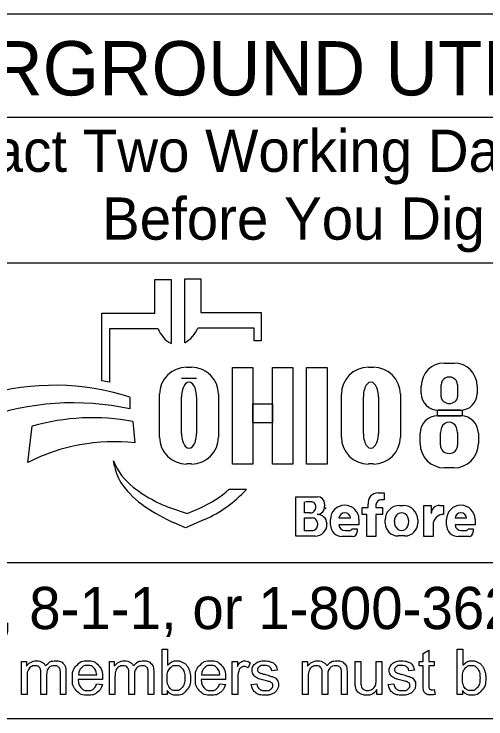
# Model space of a CAD drawing. Extents: x 0 to 34, y 0 to 22.
# Drawn here: x 3.216 to 4.78, y 2.954 to 5.292 of the extents above; entities that cross this region are included whole.
import ezdxf

# ---------------------------------------------------------------- set-up
doc = ezdxf.new("R2010")
doc.units = 0
doc.layers.add('SH_Data', color=7, linetype='Continuous')
doc.layers.add('SH_Text', color=7, linetype='Continuous')

msp = doc.modelspace()

# ---------------------------------------------------------------- linework, layer by layer
at = {"layer": 'SH_Data'}
for p, q in [((6.5766, 5.2918), (2.3266, 5.2918)), ((2.3266, 4.9502), (6.5766, 4.9502)), ((2.3266, 4.4668), (6.5766, 4.4668)), ((6.5766, 3.4722), (2.3266, 3.4722)), ((6.5766, 2.9543), (2.3266, 2.9543))]:
    msp.add_line(p, q, dxfattribs=at)
at = {"layer": 'SH_Text'}
for p, q in [((3.6827, 4.2998), (3.6827, 4.4113)), ((3.6827, 4.4113), (3.7363, 4.4113)), ((3.7363, 4.4113), (3.7363, 4.1992)), ((3.782, 4.2015), (3.782, 4.4136)), ((3.782, 4.4136), (3.8356, 4.4136)), ((3.8356, 4.4136), (3.8356, 4.3021)), ((3.8356, 4.3021), (4.0349, 4.3021)), ((4.0349, 4.3021), (4.0349, 4.2083)), ((3.5067, 4.0759), (3.5067, 4.2998)), ((3.5067, 4.2998), (3.6827, 4.2998)), ((3.5319, 4.2484), (3.5319, 4.0715)), ((3.6931, 4.2484), (3.5319, 4.2484)), ((4.0116, 4.2507), (3.8252, 4.2507)), ((4.0116, 4.2083), (4.0116, 4.2507)), ((4.0349, 4.2083), (4.0116, 4.2083)), ((3.7876, 4.1206), (3.8042, 4.1206)), ((4.3907, 4.1206), (4.4072, 4.1206)), ((4.6422, 4.1346), (4.675, 4.1346)), ((3.8209, 4.0836), (3.7711, 4.0836)), ((4.5659, 4.034), (4.5659, 4.0583)), ((4.6321, 4.0226), (4.6321, 4.0619)), ((4.6862, 4.0619), (4.6862, 4.0226)), ((4.7513, 4.0583), (4.7513, 4.034)), ((3.6, 4.0212), (3.6, 3.9824)), ((3.6982, 3.8891), (3.6982, 4.0311)), ((3.7711, 3.9005), (3.7711, 4.0229)), ((3.8209, 4.0229), (3.8209, 3.9005)), ((3.8937, 4.0311), (3.8937, 3.8891)), ((4.3012, 3.8891), (4.3012, 4.0311)), ((4.3741, 3.9005), (4.3741, 4.0229)), ((4.4239, 4.0229), (4.4239, 3.9005)), ((4.4967, 4.0311), (4.4967, 3.8891)), ((4.6953, 3.978), (4.6219, 3.978)), ((4.6201, 3.9597), (4.6974, 3.9597)), ((3.61, 3.9406), (3.6162, 3.8697)), ((3.2612, 3.8051), (3.2758, 3.9252)), ((4.5622, 3.8678), (4.5622, 3.9018)), ((4.6297, 3.8618), (4.6297, 3.9027)), ((4.6866, 3.9027), (4.6866, 3.8618)), ((4.7553, 3.9018), (4.7553, 3.8678)), ((3.5489, 3.7922), (3.5458, 3.8101)), ((3.8042, 3.7997), (3.7876, 3.7997)), ((4.4072, 3.7997), (4.3907, 3.7997)), ((4.6744, 3.7868), (4.6432, 3.7868)), ((3.9291, 3.7163), (3.9866, 3.7163)), ((4.423, 3.7041), (4.4425, 3.7041)), ((4.4425, 3.7041), (4.4425, 3.6811)), ((4.1504, 3.5605), (4.1504, 3.6913)), ((4.1504, 3.6913), (4.2216, 3.6913)), ((4.1784, 3.6378), (4.1784, 3.6747)), ((4.2036, 3.6747), (4.1823, 3.6747)), ((4.4425, 3.6806), (4.4323, 3.6806)), ((3.7307, 3.6559), (3.7901, 3.6354)), ((3.7901, 3.6354), (3.8312, 3.6532)), ((4.2454, 3.6675), (4.2454, 3.6596)), ((4.3704, 3.6327), (4.3704, 3.6557)), ((4.3704, 3.6557), (4.3897, 3.6557)), ((4.3897, 3.6557), (4.3897, 3.6661)), ((4.4158, 3.6641), (4.4158, 3.6557)), ((4.4158, 3.6557), (4.4374, 3.6557)), ((4.4374, 3.6557), (4.4374, 3.6327)), ((4.4942, 3.6623), (4.5064, 3.6623)), ((4.5745, 3.5593), (4.5745, 3.662)), ((4.5745, 3.662), (4.599, 3.662)), ((4.599, 3.662), (4.599, 3.6352)), ((4.6263, 3.662), (4.6402, 3.662)), ((4.6402, 3.662), (4.6402, 3.6324)), ((4.1978, 3.6378), (4.1784, 3.6378)), ((4.3853, 3.6327), (4.3704, 3.6327)), ((4.3853, 3.5593), (4.3853, 3.6327)), ((4.4374, 3.6327), (4.4158, 3.6327)), ((4.4158, 3.6327), (4.4158, 3.5593)), ((3.7841, 3.5884), (3.7468, 3.6049)), ((3.8474, 3.6159), (3.7841, 3.5884)), ((4.1784, 3.5784), (4.1784, 3.6212)), ((4.1784, 3.6212), (4.2039, 3.6212)), ((4.2221, 3.6031), (4.2221, 3.5968)), ((4.2534, 3.6002), (4.2534, 3.5999)), ((4.265, 3.5973), (4.265, 3.6157)), ((4.3316, 3.6197), (4.293, 3.6197)), ((4.3595, 3.6157), (4.3595, 3.5981)), ((4.4464, 3.6037), (4.4464, 3.6144)), ((4.5542, 3.6144), (4.5542, 3.6037)), ((4.6499, 3.5973), (4.6499, 3.6157)), ((4.7165, 3.6197), (4.678, 3.6197)), ((4.7444, 3.6157), (4.7444, 3.5981)), ((4.2037, 3.5784), (4.1784, 3.5784)), ((4.3595, 3.5981), (4.2931, 3.5981)), ((4.314, 3.5788), (4.3281, 3.5788)), ((4.3367, 3.5844), (4.3536, 3.5844)), ((4.3536, 3.5844), (4.3536, 3.5746)), ((4.605, 3.5975), (4.605, 3.5593)), ((4.7444, 3.5981), (4.678, 3.5981)), ((4.6989, 3.5788), (4.7131, 3.5788)), ((4.7216, 3.5844), (4.7385, 3.5844)), ((4.7385, 3.5844), (4.7385, 3.5746)), ((4.2141, 3.5605), (4.1504, 3.5605)), ((4.3383, 3.5593), (4.303, 3.5593)), ((4.4158, 3.5593), (4.3853, 3.5593)), ((4.5114, 3.5609), (4.4892, 3.5609)), ((4.605, 3.5593), (4.5745, 3.5593)), ((4.7233, 3.5593), (4.6879, 3.5593))]:
    msp.add_line(p, q, dxfattribs=at)
for points in [[(3.9401, 4.1196), (4.008, 4.1196), (4.008, 3.7996), (3.9401, 3.7996)], [(4.0722, 4.1196), (4.1402, 4.1196), (4.1402, 3.7996), (4.0722, 3.7996)], [(4.1855, 4.1196), (4.2543, 4.1196), (4.2543, 3.7996), (4.1855, 3.7996)], [(4.008, 3.9997), (4.0722, 3.9997), (4.0722, 3.9357), (4.008, 3.9357)], [(4.6198, 3.978), (4.7014, 3.978), (4.7014, 3.9596), (4.6198, 3.9596)]]:
    msp.add_lwpolyline(points, close=True, dxfattribs=at)
for points in [[(3.7234, 3.0354), (3.7064, 3.0354), (3.7064, 3.1856), (3.7248, 3.1856), (3.7248, 3.1321)], [(4.5724, 3.0673), (4.5724, 3.13), (4.5588, 3.13), (4.5588, 3.1443), (4.5724, 3.1443), (4.5724, 3.1712), (4.5908, 3.1823), (4.5908, 3.1443), (4.6092, 3.1443), (4.6092, 3.13), (4.5908, 3.13), (4.5908, 3.0662)], [(4.7025, 3.0354), (4.6855, 3.0354), (4.6855, 3.1856), (4.7039, 3.1856), (4.7039, 3.1321)], [(3.2404, 3.0354), (3.2404, 3.1443), (3.2568, 3.1443), (3.2568, 3.1289)], [(3.5317, 3.0354), (3.5317, 3.1443), (3.5482, 3.1443), (3.5482, 3.1289)], [(3.9395, 3.0354), (3.9395, 3.1443), (3.9561, 3.1443), (3.9561, 3.1278)], [(3.9986, 3.1408), (3.9921, 3.1237)], [(4.1727, 3.0354), (4.1727, 3.1443), (4.1892, 3.1443), (4.1892, 3.1289)], [(4.347, 3.0769), (4.347, 3.1443), (4.3655, 3.1443), (4.3655, 3.0839)], [(4.4167, 3.086), (4.4167, 3.1443), (4.4352, 3.1443), (4.4352, 3.0354), (4.4187, 3.0354)], [(3.3879, 3.1101), (3.3879, 3.0354), (3.3694, 3.0354), (3.3694, 3.1039)], [(3.6792, 3.1101), (3.6792, 3.0354), (3.6608, 3.0354), (3.6608, 3.1039)], [(4.0885, 3.1161), (4.0704, 3.1137)], [(4.3202, 3.1101), (4.3202, 3.0354), (4.3018, 3.0354), (4.3018, 3.1039)], [(4.5431, 3.1161), (4.525, 3.1137)], [(3.2588, 3.0918), (3.2588, 3.0354), (3.2404, 3.0354)], [(3.3234, 3.0986), (3.3234, 3.0354), (3.305, 3.0354), (3.305, 3.1061)], [(3.429, 3.1002), (3.4897, 3.1002)], [(3.5502, 3.0918), (3.5502, 3.0354), (3.5317, 3.0354)], [(3.6148, 3.0986), (3.6148, 3.0354), (3.5964, 3.0354), (3.5964, 3.1061)], [(3.837, 3.1002), (3.8977, 3.1002)], [(3.9579, 3.0924), (3.9579, 3.0354), (3.9395, 3.0354)], [(4.1912, 3.0918), (4.1912, 3.0354), (4.1727, 3.0354)], [(4.2558, 3.0986), (4.2558, 3.0354), (4.2374, 3.0354), (4.2374, 3.1061)], [(3.5091, 3.0851), (3.4279, 3.0851)], [(3.4895, 3.0706), (3.5086, 3.0682)], [(3.9171, 3.0851), (3.8359, 3.0851)], [(3.8975, 3.0706), (3.9166, 3.0682)], [(4.0021, 3.0679), (4.0203, 3.0708)], [(4.4567, 3.0679), (4.4749, 3.0708)], [(3.7234, 3.049), (3.7234, 3.0354)], [(4.4187, 3.0354), (4.4187, 3.0515)], [(4.6092, 3.0519), (4.6119, 3.0356)], [(4.7025, 3.049), (4.7025, 3.0354)]]:
    msp.add_lwpolyline(points, dxfattribs=at)
for centre, radius, start, end in [((3.7844, 4.2851), 0.0985, 201.9296, 240.7469), ((3.7338, 4.2875), 0.0985, 299.2531, 338.0704), ((3.7876, 4.0311), 0.0895, 90, 180), ((3.8042, 4.0311), 0.0895, 0, 90), ((4.3907, 4.0311), 0.0895, 90, 180), ((4.4072, 4.0311), 0.0895, 0, 90), ((4.6422, 4.0583), 0.0763, 90, 180), ((4.675, 4.0583), 0.0763, 0, 90), ((3.3786, 3.2669), 0.8191, 79.2074, 81.0007), ((3.3488, 3.2417), 0.8191, 72.1402, 106.3144), ((4.6219, 4.034), 0.056, 180, 270), ((4.6953, 4.034), 0.056, 270, 0), ((3.4119, 3.1106), 0.8919, 77.8238, 109.8274), ((3.4758, 3.2209), 0.7322, 79.44, 105.8467), ((4.6201, 3.9018), 0.0579, 90, 180), ((4.6974, 3.9018), 0.0579, 0, 90), ((3.7876, 3.8891), 0.0895, 180, 270), ((3.8042, 3.8891), 0.0895, 270, 0), ((4.3907, 3.8891), 0.0895, 180, 270), ((4.4072, 3.8891), 0.0895, 270, 0), ((3.5478, 3.2377), 0.6357, 83.8248, 116.8021), ((4.6432, 3.8678), 0.081, 180, 270), ((4.6744, 3.8678), 0.081, 270, 0), ((3.7332, 3.8822), 0.2008, 201.0457, 232.5314), ((3.6902, 3.8163), 0.1433, 189.6817, 216.0884), ((3.8238, 3.9137), 0.3088, 216.0884, 235.7167), ((3.9257, 4.1334), 0.5173, 232.5314, 241.794), ((3.6878, 3.9837), 0.3602, 293.4582, 312.0712), ((3.6878, 3.9837), 0.401, 293.4582, 317.8286), ((4.423, 3.6705), 0.0335, 90, 187.5187), ((3.8405, 3.9746), 0.3371, 241.794, 250.9821), ((4.1997, 3.6578), 0.0169, 357.8325, 90), ((4.2216, 3.6675), 0.0238, 0, 90), ((4.4323, 3.6641), 0.0165, 90, 180), ((3.9903, 4.158), 0.6044, 235.7167, 246.2325), ((4.1978, 3.6565), 0.0187, 270, 2.0582), ((4.2212, 3.6568), 0.0243, 270, 6.6529), ((4.2318, 3.6553), 0.0175, 347.4023, 0), ((4.3122, 3.6157), 0.0473, 0, 180), ((4.4942, 3.6144), 0.0478, 90, 180), ((4.5064, 3.6144), 0.0478, 0, 90), ((4.6259, 3.6352), 0.0269, 89.2449, 180), ((4.6972, 3.6157), 0.0473, 0, 180), ((4.2213, 3.6004), 0.0321, 4.0748, 90), ((4.3123, 3.6187), 0.0193, 2.9632, 177.0368), ((4.6399, 3.5975), 0.0349, 89.6033, 180), ((4.6972, 3.6187), 0.0193, 2.9632, 177.0368), ((4.2039, 3.6031), 0.0181, 0, 90), ((4.2141, 3.5999), 0.0393, 270, 0), ((4.2205, 3.6002), 0.033, 0, 11.7502), ((4.4892, 3.6037), 0.0428, 180, 270), ((4.5114, 3.6037), 0.0428, 270, 0), ((4.2037, 3.5968), 0.0184, 270, 0), ((4.303, 3.5973), 0.038, 180, 270), ((4.314, 3.5998), 0.021, 184.827, 270), ((4.3281, 3.5882), 0.00938, 270, 335.9979), ((4.6879, 3.5973), 0.038, 180, 270), ((4.6989, 3.5998), 0.021, 184.827, 270), ((4.7131, 3.5882), 0.00938, 270, 335.9979), ((4.3383, 3.5746), 0.0152, 270, 0), ((4.7233, 3.5746), 0.0152, 270, 0)]:
    msp.add_arc(centre, radius, start, end, dxfattribs=at)
for centre, major_axis, ratio, start_param, end_param in [((3.796, 4.0229), (0, 0.0484), 0.514403, 4.712389, 7.853982), ((4.399, 4.0229), (0, 0.0484), 0.514403, 4.712389, 7.853982), ((4.6591, 4.0619), (0.0271, 0), 0.969373, 0, 3.141593), ((4.6591, 4.0226), (0.0271, 0), 0.818453, 3.141593, 6.283185), ((4.6581, 3.9027), (0, 0.0358), 0.794529, 4.712389, 7.853982), ((3.796, 3.9005), (0, 0.0484), 0.514403, 1.570796, 4.712389), ((4.399, 3.9005), (0, 0.0484), 0.514403, 1.570796, 4.712389), ((4.6581, 3.8618), (0.0284, 0), 0.959837, 3.141593, 6.283185), ((4.5008, 3.6091), (0, 0.029), 0.832186, 4.712389, 7.853982), ((4.5008, 3.6091), (0, 0.0302), 0.797287, 1.570796, 4.712389)]:
    msp.add_ellipse(centre, major_axis=major_axis, ratio=ratio, start_param=start_param, end_param=end_param, dxfattribs=at)
for points in [[(3.2568, 3.1289), (3.262, 3.1369), (3.2705, 3.1418), (3.279, 3.1467), (3.2898, 3.1467), (3.3019, 3.1467), (3.3097, 3.1416), (3.3174, 3.1366), (3.3206, 3.1276), (3.3335, 3.1467), (3.3542, 3.1467), (3.3704, 3.1467), (3.3792, 3.1377), (3.3879, 3.1287), (3.3879, 3.1101)], [(3.5086, 3.0682), (3.5041, 3.0515), (3.4919, 3.0422), (3.4797, 3.033), (3.4608, 3.033), (3.4369, 3.033), (3.4229, 3.0477), (3.409, 3.0624), (3.409, 3.0889), (3.409, 3.1164), (3.4231, 3.1315), (3.4372, 3.1467), (3.4597, 3.1467), (3.4816, 3.1467), (3.4954, 3.1318), (3.5092, 3.117), (3.5092, 3.09), (3.5092, 3.0884), (3.5091, 3.0851)], [(3.5482, 3.1289), (3.5533, 3.1369), (3.5618, 3.1418), (3.5703, 3.1467), (3.5812, 3.1467), (3.5933, 3.1467), (3.601, 3.1416), (3.6088, 3.1366), (3.6119, 3.1276), (3.6249, 3.1467), (3.6456, 3.1467), (3.6618, 3.1467), (3.6705, 3.1377), (3.6792, 3.1287), (3.6792, 3.1101)], [(3.7248, 3.1321), (3.7365, 3.1467), (3.7546, 3.1467), (3.7646, 3.1467), (3.7736, 3.1426), (3.7826, 3.1386), (3.7884, 3.1313), (3.7941, 3.1239), (3.7974, 3.1136), (3.8007, 3.1033), (3.8007, 3.0915), (3.8007, 3.0635), (3.7869, 3.0483), (3.773, 3.033), (3.7537, 3.033), (3.7344, 3.033), (3.7234, 3.049)], [(3.9166, 3.0682), (3.9121, 3.0515), (3.8999, 3.0422), (3.8877, 3.033), (3.8688, 3.033), (3.8449, 3.033), (3.8309, 3.0477), (3.8169, 3.0624), (3.8169, 3.0889), (3.8169, 3.1164), (3.8311, 3.1315), (3.8452, 3.1467), (3.8677, 3.1467), (3.8895, 3.1467), (3.9034, 3.1318), (3.9172, 3.117), (3.9172, 3.09), (3.9172, 3.0884), (3.9171, 3.0851)], [(3.9561, 3.1278), (3.9624, 3.1393), (3.9678, 3.143), (3.9732, 3.1467), (3.9796, 3.1467), (3.9889, 3.1467), (3.9986, 3.1408)], [(4.0203, 3.0708), (4.0219, 3.0598), (4.0289, 3.054), (4.0359, 3.0481), (4.0486, 3.0481), (4.0613, 3.0481), (4.0675, 3.0533), (4.0736, 3.0585), (4.0736, 3.0655), (4.0736, 3.0717), (4.0682, 3.0753), (4.0644, 3.0778), (4.0493, 3.0816), (4.029, 3.0867), (4.0212, 3.0904), (4.0133, 3.0942), (4.0093, 3.1008), (4.0052, 3.1074), (4.0052, 3.1153), (4.0052, 3.1226), (4.0085, 3.1288), (4.0119, 3.135), (4.0176, 3.1391), (4.0219, 3.1423), (4.0294, 3.1445), (4.0368, 3.1467), (4.0453, 3.1467), (4.0581, 3.1467), (4.0678, 3.143), (4.0775, 3.1393), (4.0822, 3.133), (4.0868, 3.1267), (4.0885, 3.1161)], [(4.1892, 3.1289), (4.1943, 3.1369), (4.2028, 3.1418), (4.2113, 3.1467), (4.2222, 3.1467), (4.2343, 3.1467), (4.242, 3.1416), (4.2498, 3.1366), (4.2529, 3.1276), (4.2659, 3.1467), (4.2866, 3.1467), (4.3028, 3.1467), (4.3115, 3.1377), (4.3202, 3.1287), (4.3202, 3.1101)], [(4.4749, 3.0708), (4.4764, 3.0598), (4.4835, 3.054), (4.4905, 3.0481), (4.5031, 3.0481), (4.5159, 3.0481), (4.522, 3.0533), (4.5282, 3.0585), (4.5282, 3.0655), (4.5282, 3.0717), (4.5228, 3.0753), (4.519, 3.0778), (4.5039, 3.0816), (4.4836, 3.0867), (4.4757, 3.0904), (4.4679, 3.0942), (4.4638, 3.1008), (4.4598, 3.1074), (4.4598, 3.1153), (4.4598, 3.1226), (4.4631, 3.1288), (4.4664, 3.135), (4.4722, 3.1391), (4.4765, 3.1423), (4.4839, 3.1445), (4.4914, 3.1467), (4.4999, 3.1467), (4.5127, 3.1467), (4.5224, 3.143), (4.5321, 3.1393), (4.5367, 3.133), (4.5413, 3.1267), (4.5431, 3.1161)], [(4.7039, 3.1321), (4.7156, 3.1467), (4.7337, 3.1467), (4.7437, 3.1467), (4.7527, 3.1426), (4.7616, 3.1386), (4.7674, 3.1313), (4.7732, 3.1239), (4.7765, 3.1136), (4.7798, 3.1033), (4.7798, 3.0915), (4.7798, 3.0635), (4.7659, 3.0483), (4.7521, 3.033), (4.7327, 3.033), (4.7135, 3.033), (4.7025, 3.049)], [(3.305, 3.1061), (3.305, 3.1184), (3.3005, 3.1245), (3.296, 3.1306), (3.2857, 3.1306), (3.278, 3.1306), (3.2713, 3.1265), (3.2647, 3.1225), (3.2618, 3.1146), (3.2588, 3.1067), (3.2588, 3.0918)], [(3.3694, 3.1039), (3.3694, 3.115), (3.3677, 3.1198), (3.3659, 3.1247), (3.3611, 3.1277), (3.3564, 3.1306), (3.3501, 3.1306), (3.3386, 3.1306), (3.331, 3.123), (3.3234, 3.1154), (3.3234, 3.0986)], [(3.4897, 3.1002), (3.4885, 3.114), (3.4828, 3.1209), (3.474, 3.1316), (3.4599, 3.1316), (3.4472, 3.1316), (3.4386, 3.123), (3.4299, 3.1145), (3.429, 3.1002)], [(3.5964, 3.1061), (3.5964, 3.1184), (3.5919, 3.1245), (3.5874, 3.1306), (3.5771, 3.1306), (3.5693, 3.1306), (3.5627, 3.1265), (3.5561, 3.1225), (3.5531, 3.1146), (3.5502, 3.1067), (3.5502, 3.0918)], [(3.6608, 3.1039), (3.6608, 3.115), (3.659, 3.1198), (3.6572, 3.1247), (3.6525, 3.1277), (3.6478, 3.1306), (3.6415, 3.1306), (3.63, 3.1306), (3.6224, 3.123), (3.6148, 3.1154), (3.6148, 3.0986)], [(3.7232, 3.0907), (3.7232, 3.0711), (3.7285, 3.0624), (3.7372, 3.0481), (3.752, 3.0481), (3.7641, 3.0481), (3.7729, 3.0586), (3.7817, 3.0691), (3.7817, 3.0899), (3.7817, 3.1113), (3.7733, 3.1214), (3.7648, 3.1316), (3.7529, 3.1316), (3.7408, 3.1316), (3.732, 3.1211), (3.7232, 3.1105), (3.7232, 3.0907)], [(3.8977, 3.1002), (3.8965, 3.114), (3.8908, 3.1209), (3.882, 3.1316), (3.8679, 3.1316), (3.8552, 3.1316), (3.8466, 3.123), (3.8379, 3.1145), (3.837, 3.1002)], [(3.9921, 3.1237), (3.9854, 3.1277), (3.9787, 3.1277), (3.9726, 3.1277), (3.9678, 3.124), (3.9631, 3.1204), (3.961, 3.1139), (3.9579, 3.1041), (3.9579, 3.0924)], [(4.0704, 3.1137), (4.0692, 3.1221), (4.0633, 3.1268), (4.0574, 3.1316), (4.0466, 3.1316), (4.0339, 3.1316), (4.0285, 3.1274), (4.0231, 3.1231), (4.0231, 3.1175), (4.0231, 3.1139), (4.0253, 3.111), (4.0276, 3.1081), (4.0324, 3.1061), (4.0352, 3.1051), (4.0487, 3.1014), (4.0683, 3.0962), (4.076, 3.0928), (4.0838, 3.0895), (4.0882, 3.0832), (4.0926, 3.0768), (4.0926, 3.0674), (4.0926, 3.0582), (4.0872, 3.0501), (4.0819, 3.0419), (4.0717, 3.0375), (4.0615, 3.033), (4.0487, 3.033), (4.0275, 3.033), (4.0163, 3.0418), (4.0052, 3.0506), (4.0021, 3.0679)], [(4.2374, 3.1061), (4.2374, 3.1184), (4.2329, 3.1245), (4.2284, 3.1306), (4.2181, 3.1306), (4.2103, 3.1306), (4.2037, 3.1265), (4.1971, 3.1225), (4.1941, 3.1146), (4.1912, 3.1067), (4.1912, 3.0918)], [(4.3018, 3.1039), (4.3018, 3.115), (4.3, 3.1198), (4.2982, 3.1247), (4.2935, 3.1277), (4.2888, 3.1306), (4.2825, 3.1306), (4.271, 3.1306), (4.2634, 3.123), (4.2558, 3.1154), (4.2558, 3.0986)], [(4.525, 3.1137), (4.5238, 3.1221), (4.5179, 3.1268), (4.512, 3.1316), (4.5012, 3.1316), (4.4885, 3.1316), (4.4831, 3.1274), (4.4776, 3.1231), (4.4776, 3.1175), (4.4776, 3.1139), (4.4799, 3.111), (4.4821, 3.1081), (4.487, 3.1061), (4.4897, 3.1051), (4.5033, 3.1014), (4.5229, 3.0962), (4.5306, 3.0928), (4.5384, 3.0895), (4.5428, 3.0832), (4.5472, 3.0768), (4.5472, 3.0674), (4.5472, 3.0582), (4.5418, 3.0501), (4.5364, 3.0419), (4.5263, 3.0375), (4.5161, 3.033), (4.5033, 3.033), (4.482, 3.033), (4.4709, 3.0418), (4.4598, 3.0506), (4.4567, 3.0679)], [(4.7023, 3.0907), (4.7023, 3.0711), (4.7076, 3.0624), (4.7163, 3.0481), (4.7311, 3.0481), (4.7432, 3.0481), (4.752, 3.0586), (4.7608, 3.0691), (4.7608, 3.0899), (4.7608, 3.1113), (4.7523, 3.1214), (4.7439, 3.1316), (4.7319, 3.1316), (4.7199, 3.1316), (4.7111, 3.1211), (4.7023, 3.1105), (4.7023, 3.0907)], [(4.3655, 3.0839), (4.3655, 3.0695), (4.3666, 3.0645), (4.3683, 3.0572), (4.374, 3.0531), (4.3796, 3.0489), (4.3879, 3.0489), (4.3962, 3.0489), (4.4034, 3.0532), (4.4107, 3.0574), (4.4137, 3.0648), (4.4167, 3.0721), (4.4167, 3.086)], [(3.4279, 3.0851), (3.429, 3.0672), (3.4381, 3.0577), (3.4472, 3.0481), (3.4608, 3.0481), (3.471, 3.0481), (3.4782, 3.0535), (3.4853, 3.0588), (3.4895, 3.0706)], [(3.8359, 3.0851), (3.837, 3.0672), (3.8461, 3.0577), (3.8552, 3.0481), (3.8688, 3.0481), (3.879, 3.0481), (3.8862, 3.0535), (3.8933, 3.0588), (3.8975, 3.0706)], [(4.4187, 3.0515), (4.406, 3.033), (4.3842, 3.033), (4.3746, 3.033), (4.3662, 3.0367), (4.3579, 3.0404), (4.3539, 3.046), (4.3498, 3.0516), (4.3482, 3.0597), (4.347, 3.0651), (4.347, 3.0769)], [(4.6119, 3.0356), (4.6041, 3.0339), (4.598, 3.0339), (4.5879, 3.0339), (4.5824, 3.0371), (4.5769, 3.0403), (4.5746, 3.0455), (4.5724, 3.0507), (4.5724, 3.0673)], [(4.5908, 3.0662), (4.5908, 3.0583), (4.5918, 3.056), (4.5927, 3.0538), (4.5949, 3.0524), (4.5971, 3.0511), (4.6012, 3.0511), (4.6042, 3.0511), (4.6092, 3.0519)]]:
    msp.add_open_spline(points, degree=3, dxfattribs=at)

# ---------------------------------------------------------------- texts
for s, height, p in [('UNDERGROUND UTILITIES', 0.18, (2.4548, 5.0221)), ('Contact Two Working Days', 0.14, (2.7463, 4.7686)), ('Before You Dig', 0.14, (3.5075, 4.5436)), ('OHIO811, 8-1-1, or 1-800-362-2764', 0.14, (2.3711, 3.2521))]:
    msp.add_text(s, height=height, dxfattribs=at).set_placement(p)

doc.saveas('drawing.dxf')
